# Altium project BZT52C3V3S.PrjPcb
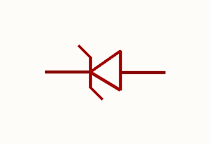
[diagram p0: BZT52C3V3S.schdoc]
1 sheet, 1 parts. Net scope: global (net labels, ports and power ports of the same name join across sheets).

## Sheet BZT52C3V3S.schdoc
size 127 x 101 mm

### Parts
D?  bzt52c3v3s_c188195  [SOD-323_L1.8-W1.3-LS2.5-RD]  (value not drawn)

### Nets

Not connected (* = marked no-connect by the designer): D? 1 2

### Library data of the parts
D? = bzt52c3v3s_c188195: 二极管配置:1个独立式;稳压值(标称值):3.3V;稳压值(范围值):3.1V~3.5V;耗散功率(Pd):200mW;; Manufacturer: CJ(江苏长电/长晶); AddInBom: yes; ModelId: db63db13d9e342eb939127d413d6200b; ModelTransform: 104.3305,51.181,0,0,0,0,0,-0.004,0; Diode Configuration: 1个独立式; Zener Voltage(Nom): 3.3V; Reverse Leakage Current (Ir): 5uA@1V; Pd - Power Dissipation: 200mW; Impedance(Zzt): 95Ω; Impedance(Zzk): 600Ω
